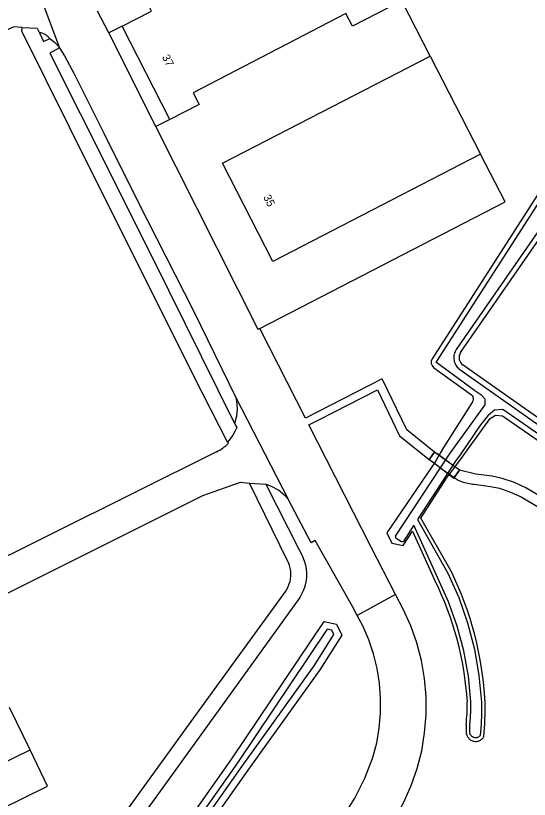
# Model space of a CAD drawing. Extents: x 158132 to 159658, y 385257 to 387209.
# Drawn here: x 159162.7 to 159226.8, y 386283.7 to 386381.6 of the extents above; entities that cross this region are included whole.
import ezdxf

# ---------------------------------------------------------------- set-up
doc = ezdxf.new("R2010")
doc.units = 0
for name, color, linetype in [('IMGEO_Dek', 7, 'Continuous'), ('IMGEO_Groenvoorziening', 7, 'Continuous'), ('IMGEO_Pand', 7, 'Continuous'), ('IMGEO_Pand_nummerreeks', 7, 'Continuous'), ('IMGEO_Parkeervlak_open', 7, 'Continuous'), ('IMGEO_Rijbaan_lokaal_gesloten', 7, 'Continuous'), ('IMGEO_Rijbaan_lokaal_open', 7, 'Continuous'), ('IMGEO_Voetpad_onverhard', 7, 'Continuous'), ('IMGEO_Voetpad_open', 7, 'Continuous'), ('IMGEO_Waterloop', 7, 'Continuous')]:
    doc.layers.add(name, color=color, linetype=linetype)

msp = doc.modelspace()

# ---------------------------------------------------------------- linework, layer by layer
at = {"layer": 'IMGEO_Dek'}
msp.add_lwpolyline([(159214.996, 386327.112), (159214.323, 386326.185), (159214.968, 386325.716), (159217.399, 386323.868), (159218.11, 386324.847)], close=True, dxfattribs=at)
at = {"layer": 'IMGEO_Groenvoorziening'}
for points in [[(159218.249, 386339.522), (159231.93, 386359.273), (159234.772, 386363.689), (159234.979, 386365.404), (159234.401, 386365.97), (159233.421, 386366.204), (159231.477, 386365.219), (159230.175, 386362.855), (159214.684, 386338.754)], [(159214.875, 386337.683), (159219.589, 386334.249)], [(159278.549, 386297.198), (159257.713, 386310.385), (159218.548, 386337.954)], [(159219.736, 386333.394), (159216.098, 386327.673), (159215.529, 386326.688), (159214.968, 386325.716), (159214.948, 386325.689), (159214.634, 386325.257), (159209.012, 386317.015), (159209.642, 386315.727), (159211.08, 386315.424), (159212.249, 386317.241), (159214.987, 386311.156)], [(159217.062, 386312.216), (159213.289, 386318.855), (159216.494, 386323.834), (159216.861, 386324.339), (159218.001, 386325.903), (159221.923, 386331.285), (159222.599, 386331.73), (159223.475, 386331.636), (159276.729, 386294.754)], [(159165.33, 386250), (159161.327, 386244.313), (159159.507, 386243.797), (159159.345, 386244.053), (159158.827, 386244.873), (159162.396, 386250), (159170.003, 386260.929), (159189.652, 386288.81), (159201.189, 386305.946), (159202.72, 386305.624), (159203.385, 386304.266), (159200.668, 386299.926), (159191.667, 386287.402), (159171.809, 386259.206), (159165.33, 386250)], [(159218.941, 386293.015), (159218.934, 386292.288), (159218.93, 386292.183), (159218.934, 386292.078), (159218.947, 386291.973), (159218.97, 386291.871), (159219.002, 386291.77), (159219.042, 386291.673), (159219.09, 386291.58), (159219.147, 386291.491), (159219.211, 386291.408), (159219.282, 386291.331), (159219.36, 386291.26), (159219.443, 386291.196), (159219.532, 386291.14), (159219.625, 386291.091), (159219.723, 386291.052), (159219.823, 386291.02), (159219.926, 386290.998), (159220.03, 386290.985), (159220.135, 386290.981), (159220.24, 386290.986), (159220.344, 386291), (159220.447, 386291.024), (159220.547, 386291.056), (159220.644, 386291.097), (159220.737, 386291.146), (159220.825, 386291.204), (159220.908, 386291.268), (159220.984, 386291.34), (159221.055, 386291.418), (159221.118, 386291.502), (159221.146, 386291.549)]]:
    msp.add_lwpolyline(points, dxfattribs=at)
for centre, radius, start, end in [((159219.207, 386338.892), 1.147, 146.69211, 234.89999), ((159215.337, 386338.318), 0.785, 146.26711, 233.95631), ((159219.222, 386333.746), 0.623, 325.58879, 53.92217), ((159179.784, 386293.845), 41.559, 2.81412, 26.23531), ((159179.504, 386293.453), 39.655, 3.54988, 26.51539), ((159183.566, 386296.189), 35.517, 354.8728, 359.54661), ((159186.94, 386294.879), 34.368, 354.43944, 1.67714)]:
    msp.add_arc(centre, radius, start, end, dxfattribs=at)
at = {"layer": 'IMGEO_Pand'}
for points in [[(159175.962, 386380.293), (159179.634, 386382.147), (159179.327, 386382.743), (159185.931, 386386.107)], [(159210.917, 386383.428), (159204.73, 386380.276), (159203.913, 386381.854), (159184.817, 386371.979), (159185.581, 386370.502), (159181.914, 386368.631)], [(159181.914, 386368.631), (159175.962, 386380.293)], [(159220.742, 386364.283), (159194.8, 386350.917), (159188.48, 386363.184), (159214.422, 386376.549)], [(159214.422, 386376.549), (159220.742, 386364.283)]]:
    msp.add_lwpolyline(points, dxfattribs=at)
at = {"layer": 'IMGEO_Parkeervlak_open'}
msp.add_lwpolyline([(159143.317, 386279.598), (159145.544, 386275.043), (159166.651, 386285.382), (159164.449, 386289.929)], dxfattribs=at)
at = {"layer": 'IMGEO_Rijbaan_lokaal_gesloten'}
for points in [[(159164.297, 386387.8), (159168.141, 386377.563)], [(159174.277, 386379.433), (159172.88, 386382.172)], [(159163.452, 386380.131), (159162.434, 386380.179), (159160.052, 386379.107), (159160.256, 386378.722), (159149.707, 386373.549), (159149.172, 386373.703), (159145.189, 386371.704), (159138.555, 386368.375)], [(159163.452, 386380.131), (159165.359, 386380.029), (159165.626, 386379.459)], [(159166.925, 386378.739), (159166.814, 386378.867), (159166.693, 386378.985), (159166.561, 386379.091), (159166.421, 386379.186), (159166.273, 386379.268), (159166.118, 386379.337), (159165.958, 386379.392), (159165.794, 386379.433), (159165.626, 386379.459)], [(159180.168, 386367.751), (159174.277, 386379.433)], [(159166.925, 386378.739), (159167.256, 386378.51), (159167.521, 386378.285), (159167.766, 386378.038), (159167.991, 386377.773), (159168.141, 386377.563)], [(159168.141, 386377.563), (159168.193, 386377.49), (159168.768, 386376.574), (159169.971, 386374.315), (159173.689, 386366.918), (159177.973, 386358.291), (159184.879, 386344.72), (159190.157, 386333.929)], [(159193.173, 386342.533), (159192.948, 386342.407), (159180.168, 386367.751)], [(159210.125, 386309.329), (159207.064, 386315.221), (159199.289, 386330.508), (159200.448, 386331.098), (159202.383, 386332.082), (159207.849, 386334.862), (159210.613, 386329.132), (159214.323, 386326.185), (159214.996, 386327.112), (159211.53, 386329.865), (159208.455, 386336.24), (159201.951, 386332.932), (159198.857, 386331.358), (159193.173, 386342.533)], [(159190.157, 386333.929), (159190.249, 386333.465), (159190.303, 386332.996), (159190.319, 386332.523), (159190.296, 386332.051), (159190.235, 386331.583), (159190.136, 386331.121), (159189.999, 386330.668)], [(159190.157, 386333.929), (159196.678, 386321.21)], [(159189.999, 386330.668), (159190.281, 386330.18), (159190.042, 386329.687), (159189.765, 386329.214), (159189.452, 386328.763), (159189.105, 386328.339)], [(159189.105, 386328.339), (159189.241, 386328.198)], [(159187.744, 386327.14), (159146.313, 386306.52)], [(159148.667, 386303.059), (159186.019, 386321.678), (159190.748, 386323.367), (159191.885, 386323.216)], [(159191.885, 386323.216), (159193.902, 386323.084)], [(159196.678, 386321.21), (159196.364, 386321.606), (159195.497, 386322.34), (159194.694, 386322.764), (159193.902, 386323.084)], [(159205.329, 386306.689), (159204.731, 386307.817), (159200.077, 386316.074), (159199.574, 386315.789), (159196.678, 386321.21)], [(159170.034, 386224.271), (159170.744, 386225.279), (159175.909, 386232.566), (159181.095, 386239.838), (159201.285, 386268.363), (159208.814, 386279.502), (159210.067, 386281.395), (159211.157, 386283.387), (159212.076, 386285.464), (159212.818, 386287.61), (159213.377, 386289.811), (159213.749, 386292.051), (159213.932, 386294.314), (159213.925, 386296.585), (159213.727, 386298.847), (159213.34, 386301.085), (159212.767, 386303.282), (159212.011, 386305.423), (159211.078, 386307.494), (159210.125, 386309.329)], [(159210.125, 386309.329), (159205.329, 386306.689)], [(159165.558, 386227.517), (159175.438, 386241.635), (159184.786, 386254.949), (159194.152, 386268.251), (159203.536, 386281.54), (159205.023, 386283.901), (159206.28, 386286.392), (159207.296, 386288.99), (159207.762, 386290.801), (159208.078, 386292.645), (159208.24, 386294.508), (159208.249, 386296.378), (159208.103, 386298.243), (159207.804, 386300.089), (159207.355, 386301.904), (159206.757, 386303.676), (159206.016, 386305.393), (159205.329, 386306.689)]]:
    msp.add_lwpolyline(points, dxfattribs=at)
msp.add_arc((159185.086, 386332.489), 5.973, 296.42408, 314.0772, dxfattribs=at)
at = {"layer": 'IMGEO_Rijbaan_lokaal_open'}
for points in [[(159164.449, 386289.929), (159161.883, 386295.226)], [(159143.317, 386279.598), (159164.449, 386289.929)]]:
    msp.add_lwpolyline(points, dxfattribs=at)
at = {"layer": 'IMGEO_Voetpad_onverhard'}
msp.add_lwpolyline([(159228.633, 386321.327), (159226.38, 386322.651), (159224.969, 386323.286), (159223.453, 386323.824), (159222.196, 386324.096), (159220.153, 386324.345), (159218.11, 386324.847), (159217.437, 386323.921), (159217.932, 386323.6), (159218.563, 386323.367), (159219.756, 386323.119), (159219.921, 386323.078), (159221.982, 386322.827), (159223.101, 386322.585), (159224.489, 386322.092), (159225.788, 386321.507), (159227.97, 386320.225)], dxfattribs=at)
at = {"layer": 'IMGEO_Voetpad_open'}
for points in [[(159214.422, 386376.549), (159210.917, 386383.428)], [(159189.105, 386328.339), (159186.001, 386334.477), (159175.768, 386354.886), (159169.365, 386367.686), (159163.425, 386379.653), (159163.452, 386380.131)], [(159175.962, 386380.293), (159174.277, 386379.433)], [(159165.626, 386379.459), (159166.134, 386378.388), (159166.925, 386378.739)], [(159168.141, 386377.563), (159166.906, 386376.922), (159170.707, 386369.399), (159179.672, 386351.536), (159189.999, 386330.668)], [(159181.914, 386368.631), (159180.168, 386367.751)], [(159193.173, 386342.533), (159223.806, 386358.337), (159220.742, 386364.283)], [(159214.323, 386326.185), (159214.968, 386325.716), (159215.931, 386324.984), (159216.861, 386324.339), (159217.437, 386323.921), (159218.11, 386324.847), (159217.537, 386325.264), (159215.254, 386326.925), (159214.996, 386327.112), (159214.323, 386326.185)], [(159108.848, 386282.056), (159117.567, 386273.343), (159130.648, 386260.403), (159140.343, 386250.704), (159148.101, 386242.94), (159161.049, 386260.864), (159173.188, 386277.68), (159184.907, 386293.934), (159196.39, 386309.759), (159196.565, 386310.04), (159196.715, 386310.335), (159196.838, 386310.643), (159196.932, 386310.96), (159196.997, 386311.285), (159197.033, 386311.614), (159197.039, 386311.945), (159197.015, 386312.275), (159196.962, 386312.602), (159196.879, 386312.923), (159196.768, 386313.235), (159196.629, 386313.536), (159191.885, 386323.216)], [(159193.902, 386323.084), (159198.038, 386314.973), (159198.395, 386314.26), (159198.59, 386313.845), (159198.747, 386313.412), (159198.865, 386312.966), (159198.944, 386312.51), (159198.983, 386312.048), (159198.981, 386311.583), (159198.938, 386311.119), (159198.855, 386310.66), (159198.732, 386310.21), (159198.571, 386309.772), (159198.373, 386309.351), (159198.138, 386308.948), (159189.781, 386297.34), (159177.033, 386279.71), (159164.932, 386263.075), (159149.388, 386241.446), (159164.231, 386225.621)]]:
    msp.add_lwpolyline(points, dxfattribs=at)
at = {"layer": 'IMGEO_Waterloop'}
for points in [[(159251.805, 386312.834), (159223.497, 386332.439), (159222.464, 386332.331), (159222.259, 386332.154), (159221.656, 386331.635), (159220.725, 386330.513), (159218.169, 386326.771), (159217.599, 386325.988), (159212.869, 386318.675), (159216.66, 386312.003), (159218.019, 386308.934), (159219.122, 386305.765), (159219.964, 386302.516), (159220.537, 386299.21), (159220.839, 386295.867), (159220.851, 386294.479), (159220.806, 386293.092), (159220.705, 386291.708), (159220.659, 386291.658), (159220.612, 386291.614), (159220.561, 386291.574), (159220.505, 386291.538), (159220.449, 386291.508), (159220.389, 386291.483), (159220.326, 386291.462), (159220.262, 386291.447), (159220.199, 386291.439), (159220.133, 386291.436), (159220.067, 386291.438), (159220.002, 386291.447), (159219.94, 386291.46), (159219.876, 386291.48), (159219.815, 386291.504), (159219.759, 386291.534), (159219.703, 386291.569), (159219.652, 386291.609), (159219.603, 386291.654), (159219.559, 386291.701), (159219.519, 386291.753), (159219.484, 386291.807), (159219.455, 386291.864), (159219.429, 386291.926), (159219.409, 386291.99), (159219.395, 386292.051), (159219.387, 386292.115), (159219.385, 386292.183), (159219.388, 386292.277), (159219.395, 386292.993), (159219.469, 386293.967), (159219.516, 386294.943), (159219.537, 386295.92), (159219.21, 386299.12), (159218.629, 386302.282), (159217.795, 386305.388), (159216.716, 386308.418), (159215.398, 386311.351), (159212.415, 386317.979), (159211.062, 386315.902), (159210.847, 386315.902), (159210.194, 386316.323), (159210.09, 386316.589), (159216.85, 386326.832), (159217.278, 386327.42), (159221.327, 386333.022), (159221.327, 386333.696), (159220.877, 386334.168), (159220.138, 386334.663), (159220.089, 386334.709), (159220.039, 386334.752), (159219.986, 386334.793), (159215.271, 386338.227), (159215.264, 386338.233), (159215.257, 386338.24), (159215.25, 386338.247), (159215.244, 386338.255), (159215.239, 386338.263), (159215.235, 386338.272), (159215.231, 386338.281), (159215.229, 386338.29), (159215.227, 386338.3), (159215.225, 386338.309), (159215.225, 386338.319), (159215.226, 386338.329), (159215.227, 386338.338), (159215.229, 386338.348), (159215.232, 386338.357), (159215.236, 386338.366), (159215.241, 386338.375), (159215.246, 386338.383), (159230.754, 386362.51)], [(159231.37, 386359.647), (159217.691, 386339.899), (159217.611, 386339.766), (159217.542, 386339.626), (159217.485, 386339.48), (159217.441, 386339.33), (159217.41, 386339.177), (159217.392, 386339.022), (159217.387, 386338.866), (159217.396, 386338.71), (159217.419, 386338.556), (159217.454, 386338.404), (159217.502, 386338.255), (159217.563, 386338.111), (159217.636, 386337.973), (159217.721, 386337.842), (159217.816, 386337.719), (159217.922, 386337.604), (159218.037, 386337.498), (159218.161, 386337.403), (159257.339, 386309.825)], [(159159.89, 386244.799), (159160.8, 386245.057), (159164.627, 386250.495), (159171.106, 386259.701), (159190.967, 386287.9), (159199.954, 386300.405), (159202.403, 386304.317), (159202.133, 386304.869), (159201.579, 386304.986), (159190.36, 386288.322), (159170.707, 386260.436), (159163.101, 386249.509), (159159.858, 386244.85), (159159.89, 386244.799)]]:
    msp.add_lwpolyline(points, dxfattribs=at)

# ---------------------------------------------------------------- texts
at = {"layer": 'IMGEO_Pand_nummerreeks'}
for s, rotation, p in [('37', 297.02048, (159180.898, 386376.437)), ('35', 296.92516, (159193.547, 386358.953))]:
    msp.add_text(s, height=1, rotation=rotation, dxfattribs=at).set_placement(p)

doc.saveas('drawing.dxf')
